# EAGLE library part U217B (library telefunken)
TRIAC CONTROL CIRCUIT
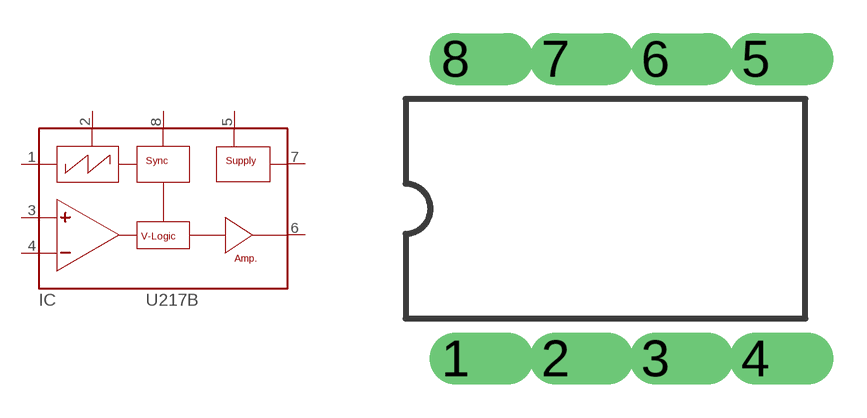
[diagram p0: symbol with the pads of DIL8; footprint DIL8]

Designator prefix IC

## U217B  [DIL8]
1  RI
2  RO
3  +
4  -
5  VS
6  PO
7  VN
8  SY

## Footprint DIL8 (pad centres in mm)
Dual In Line
drill 0.813 offset: 1 -3.81,-3.81; 2 -1.27,-3.81; 3 1.27,-3.81; 4 3.81,-3.81; 5 3.81,3.81; 6 1.27,3.81; 7 -1.27,3.81; 8 -3.81,3.81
